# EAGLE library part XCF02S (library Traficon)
Xilinx Platform Flash In-System Programmable Configuration PROMS Digikey reference: 122-1287-5-ND
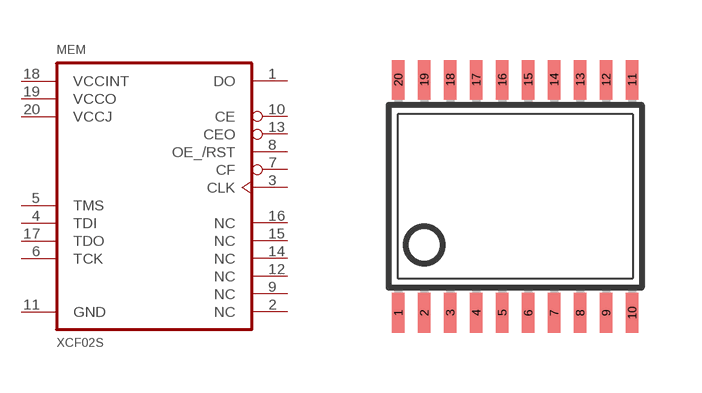
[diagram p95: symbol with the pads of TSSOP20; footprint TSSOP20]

Designator prefix MEM

## XCF02S-VO20  [TSSOP20]
1  DO
2  NC
3  CLK
4  TDI
5  TMS
6  TCK
7  CF
8  OE_/RST
9  NC
10  CE
11  GND
12  NC
13  CEO
14  NC
15  NC
16  NC
17  TDO
18  VCCINT
19  VCCO
20  VCCJ

## Footprint TSSOP20 (pad centres in mm)
Thin Shrink Small Outline Plastic 20 MAX3223-MAX3243.pdf
smd 0.305 x 0.991: 1 -2.925,-2.918; 2 -2.275,-2.918; 3 -1.625,-2.918; 4 -0.975,-2.918; 5 -0.325,-2.918; 6 0.325,-2.918; 7 0.975,-2.918; 8 1.625,-2.918; 9 2.275,-2.918; 10 2.925,-2.918; 11 2.925,2.918; 12 2.275,2.918; 13 1.625,2.918; 14 0.975,2.918; 15 0.325,2.918; 16 -0.325,2.918; 17 -0.975,2.918; 18 -1.625,2.918; 19 -2.275,2.918; 20 -2.925,2.918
